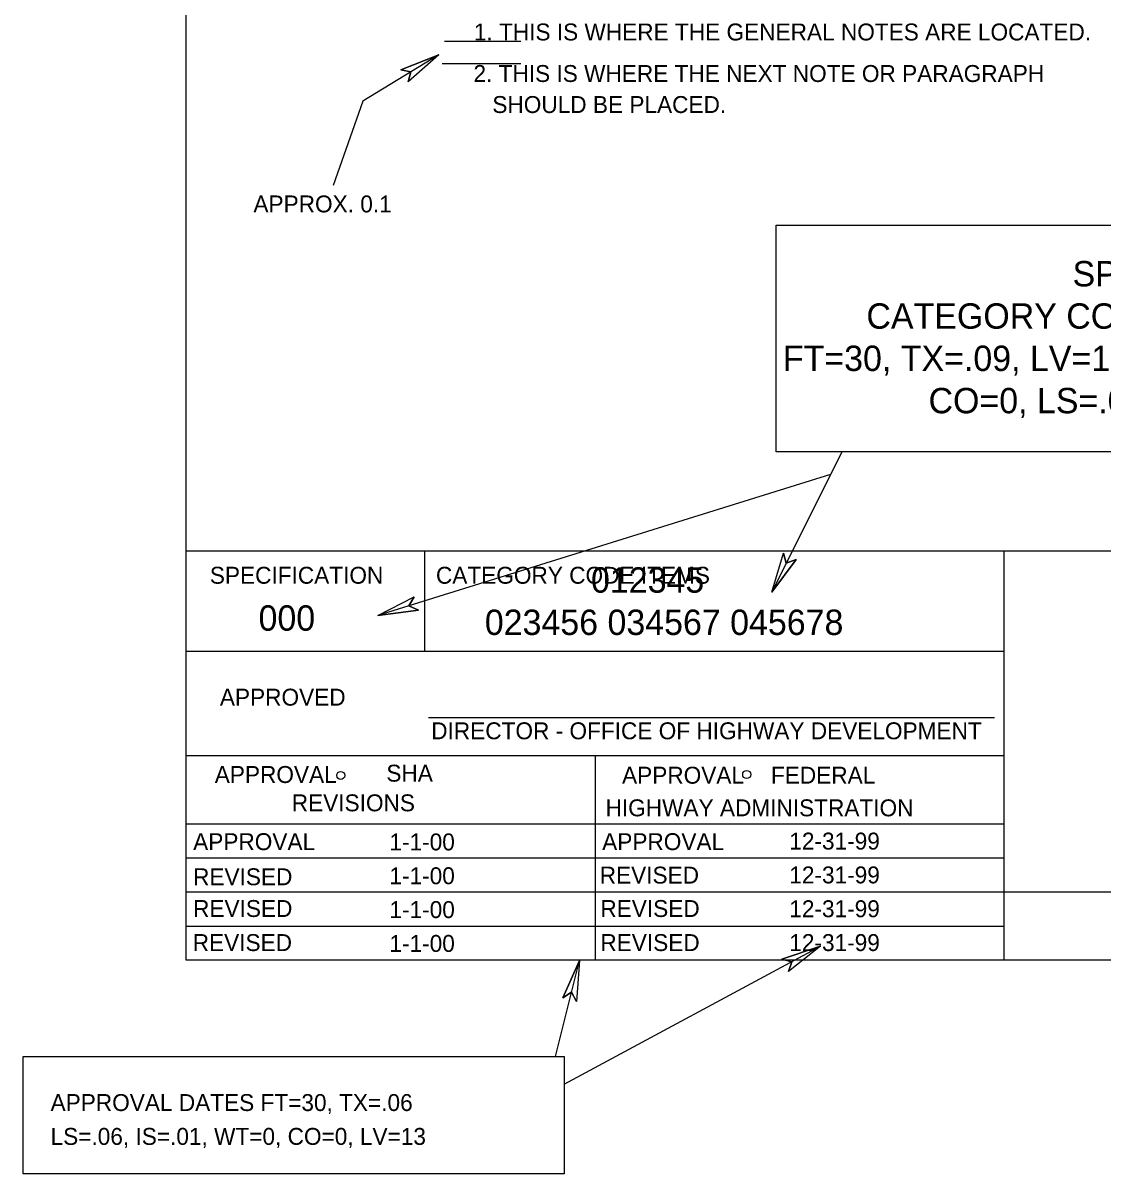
# Model space of a CAD drawing. Extents: x 0 to 1549163, y -476626 to 622136.
# Drawn here: x -0.185 to 3.645, y 5.179 to 9.261 of the extents above; entities that cross this region are included whole.
import ezdxf

# ---------------------------------------------------------------- set-up
doc = ezdxf.new("R2010")
doc.units = 0
for name, color, linetype in [('BORD-LINE', 7, 'Continuous'), ('DETL-DIMS', 7, 'Continuous'), ('DETL-NOTE', 7, 'Continuous'), ('TTLB-TEXT', 7, 'Continuous'), ('USER-BORD', 7, 'Continuous')]:
    doc.layers.add(name, color=color, linetype=linetype)

msp = doc.modelspace()

# ---------------------------------------------------------------- linework, layer by layer
at = {"layer": 'BORD-LINE'}
for p, q in [((7.7685, 7.3883), (0.3943, 7.3883)), ((1.2535, 6.7985), (3.2604, 6.7985)), ((0.3943, 6.6629), (1.2405, 6.6629)), ((0.3943, 5.9375), (0.3943, 6.6629)), ((1.2405, 6.0584), (3.2956, 6.0584))]:
    msp.add_line(p, q, dxfattribs=at)
at = {"layer": 'DETL-DIMS'}
for p, q in [((1.2901, 9.1483), (1.0203, 8.9841)), ((1.2901, 9.1483), (1.1548, 9.0955)), ((1.2901, 9.1483), (1.181, 9.0524)), ((1.1548, 9.0955), (1.191, 9.088)), ((1.191, 9.088), (1.181, 9.0524)), ((1.0203, 8.9841), (0.9148, 8.6849)), ((2.7192, 7.74), (2.4706, 7.2422)), ((2.6792, 7.6599), (1.0734, 7.16)), ((2.4706, 7.2422), (2.512, 7.3814)), ((2.4706, 7.2422), (2.557, 7.3589)), ((2.5224, 7.346), (2.512, 7.3814)), ((2.557, 7.3589), (2.5224, 7.346)), ((1.0734, 7.16), (1.2024, 7.2266)), ((1.1842, 7.1945), (1.2024, 7.2266)), ((1.2174, 7.1784), (1.1842, 7.1945)), ((1.0734, 7.16), (1.2174, 7.1784)), ((1.7345, 5.4977), (2.6438, 5.9866)), ((2.6438, 5.9866), (2.5059, 5.9411)), ((2.6438, 5.9866), (2.5298, 5.8967)), ((1.7034, 5.5961), (1.7884, 5.9359)), ((1.7884, 5.9359), (1.7293, 5.8033)), ((1.7884, 5.9359), (1.7782, 5.7911)), ((2.5059, 5.9411), (2.5416, 5.9317)), ((2.5416, 5.9317), (2.5298, 5.8967)), ((1.7293, 5.8033), (1.7603, 5.8234)), ((1.7603, 5.8234), (1.7782, 5.7911))]:
    msp.add_line(p, q, dxfattribs=at)
for points in [[(1.1548, 9.0955), (1.2901, 9.1483), (1.181, 9.0524), (1.191, 9.088)], [(2.557, 7.3589), (2.4706, 7.2422), (2.512, 7.3814), (2.5224, 7.346)], [(1.2174, 7.1784), (1.0734, 7.16), (1.2024, 7.2266), (1.1842, 7.1945)], [(2.5059, 5.9411), (2.6438, 5.9866), (2.5298, 5.8967), (2.5416, 5.9317)], [(1.7293, 5.8033), (1.7884, 5.9359), (1.7782, 5.7911), (1.7603, 5.8234)]]:
    msp.add_lwpolyline(points, close=True, dxfattribs=at)
at = {"layer": 'DETL-NOTE'}
for p, q in [((1.3106, 9.1971), (1.5804, 9.1971)), ((1.3018, 9.1171), (1.5804, 9.1171))]:
    msp.add_line(p, q, dxfattribs=at)
for centre in [(0.9422, 6.5926), (2.3819, 6.5959)]:
    msp.add_ellipse(centre, major_axis=(0, -0.0143), ratio=0.999903, dxfattribs=at)
at = {"layer": 'TTLB-TEXT'}
msp.add_line((7.7685, 7.3883), (0.3943, 7.3883), dxfattribs=at)
for points in [[(0.3943, 16.2906), (7.7685, 16.2906), (7.7685, 5.9375), (0.3943, 5.9375)], [(2.4865, 8.5442), (4.7055, 8.5442), (4.7055, 7.74), (2.4865, 7.74)], [(-0.1847, 5.5961), (1.7345, 5.5961), (1.7345, 5.1791), (-0.1847, 5.1791)]]:
    msp.add_lwpolyline(points, close=True, dxfattribs=at)
for centre in [(0.9422, 6.5926), (2.3819, 6.5959)]:
    msp.add_ellipse(centre, major_axis=(0, -0.0143), ratio=0.999903, dxfattribs=at)
at = {"layer": 'USER-BORD'}
for p, q in [((7.7685, 7.3883), (0.3943, 7.3883)), ((1.2405, 7.0336), (1.2405, 7.3883)), ((3.2956, 5.9375), (3.2956, 7.3883)), ((0.3943, 7.0336), (3.2956, 7.0336)), ((0.3943, 6.6629), (3.2956, 6.6629)), ((1.8449, 6.6629), (1.8449, 5.9375)), ((0.3943, 6.4211), (3.2956, 6.4211)), ((0.3943, 6.3002), (3.2956, 6.3002)), ((0.3943, 6.1793), (3.2956, 6.1793)), ((3.2956, 6.1793), (7.7685, 6.1793)), ((0.3943, 6.0584), (3.2956, 6.0584))]:
    msp.add_line(p, q, dxfattribs=at)

# ---------------------------------------------------------------- texts
at = {"layer": 'DETL-NOTE'}
for s, p in [('1. THIS IS WHERE THE GENERAL NOTES ARE LOCATED.', (1.4142, 9.1994)), ('2. THIS IS WHERE THE NEXT NOTE OR PARAGRAPH', (1.4129, 9.0521)), ('   SHOULD BE PLACED.', (1.4129, 8.9421)), ('APPROX. 0.1', (0.6324, 8.5895)), ('CATEGORY CODE ITEMS ', (1.2798, 7.2725))]:
    msp.add_text(s, height=0.06, dxfattribs=at).set_placement(p)
at = {"layer": 'TTLB-TEXT'}
for s, height, p in [('SPECIFICATION,', 0.09, (3.5376, 8.327)), (' CATEGORY CODE ITEMS, ', 0.09, (2.7731, 8.177)), ('FT=30, TX=.09, LV=13, WT=0,', 0.09, (2.5102, 8.027)), (' CO=0, LS=.06, IS=.01', 0.09, (2.9933, 7.877)), ('SPECIFICATION', 0.06, (0.4779, 7.2725)), ('CATEGORY CODE ITEMS ', 0.06, (1.2798, 7.2725)), ('            012345', 0.09, (1.4285, 7.2408)), ('000', 0.09, (0.6506, 7.1059)), ('023456 034567 045678', 0.09, (1.4531, 7.0908)), ('APPROVED', 0.06, (0.5135, 6.8402)), ('DIRECTOR - OFFICE OF HIGHWAY DEVELOPMENT', 0.06, (1.263, 6.7209)), ('APPROVAL', 0.06, (0.4953, 6.5659)), ('SHA', 0.06, (1.1039, 6.5706)), ('APPROVAL', 0.06, (1.9398, 6.5634)), ('FEDERAL', 0.06, (2.4679, 6.5635)), ('REVISIONS', 0.06, (0.7684, 6.4654)), ('HIGHWAY ADMINISTRATION', 0.06, (1.8813, 6.4477)), ('APPROVAL', 0.06, (0.4187, 6.3277)), ('1-1-00', 0.06, (1.1148, 6.3268)), ('APPROVAL', 0.06, (1.8693, 6.3277)), ('12-31-99', 0.06, (2.533, 6.3298)), ('1-1-00', 0.06, (1.1148, 6.2068)), ('12-31-99', 0.06, (2.533, 6.2098)), ('1-1-00', 0.06, (1.1148, 6.0868)), ('12-31-99', 0.06, (2.533, 6.0898)), ('1-1-00', 0.06, (1.1148, 5.9668)), ('12-31-99', 0.06, (2.533, 5.9698)), ('APPROVAL DATES FT=30, TX=.06', 0.06, (-0.087, 5.4024)), ('LS=.06, IS=.01, WT=0, CO=0, LV=13 ', 0.06, (-0.087, 5.2824))]:
    msp.add_text(s, height=height, dxfattribs=at).set_placement(p)
at = {"layer": 'USER-BORD'}
for s, p in [('DIRECTOR - OFFICE OF HIGHWAY DEVELOPMENT', (1.263, 6.7209)), ('REVISED', (0.4184, 6.2032)), ('REVISED', (1.8606, 6.2091)), ('REVISED', (0.4184, 6.0906)), ('REVISED', (1.8629, 6.0906)), ('REVISED', (0.4171, 5.9698)), ('REVISED', (1.8629, 5.9698))]:
    msp.add_text(s, height=0.06, dxfattribs=at).set_placement(p)

doc.saveas('drawing.dxf')
